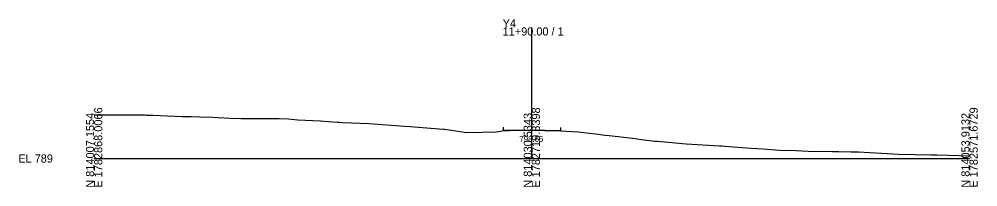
# Model space of a CAD drawing. Extents: x -26 to 3903, y -10 to 9562.
# Drawn here: x 2274.3 to 2602.8, y 490.3 to 547.7 of the extents above; entities that cross this region are included whole.
import ezdxf

# ---------------------------------------------------------------- set-up
doc = ezdxf.new("R2010")
doc.units = 0
for name, color, linetype in [('Exist Cross Section Cell', 7, 'Continuous'), ('Exist XS Center Line Elevation Label', 7, 'Continuous'), ('Exist XS Ground Line', 7, 'Continuous'), ('Prop XS EOT Tick Mark', 7, 'Continuous'), ('Prop XS Finish Grade Pavement', 7, 'Continuous')]:
    doc.layers.add(name, color=color, linetype=linetype)

msp = doc.modelspace()

# ---------------------------------------------------------------- linework, layer by layer
at = {"layer": 'Exist Cross Section Cell'}
for p, q in [((2450, 500), (2450, 544.86)), ((2300, 500), (2450, 500)), ((2450, 500), (2600, 500))]:
    msp.add_line(p, q, dxfattribs=at)
at = {"layer": 'Exist XS Ground Line'}
for p, q in [((2300, 514.94), (2302.74, 514.95)), ((2302.74, 514.95), (2317.36, 514.88)), ((2317.36, 514.88), (2317.93, 514.87)), ((2317.93, 514.87), (2320.13, 514.79)), ((2320.13, 514.79), (2330.17, 514.36)), ((2330.17, 514.36), (2333.2, 514.35)), ((2333.2, 514.35), (2336.09, 514.24)), ((2336.09, 514.24), (2340.7, 514.17)), ((2340.7, 514.17), (2342.54, 514.02)), ((2342.54, 514.02), (2346.5, 513.74)), ((2346.5, 513.74), (2350.32, 513.72)), ((2350.32, 513.72), (2355.28, 513.69)), ((2355.28, 513.69), (2363.4, 513.66)), ((2363.4, 513.66), (2366.62, 513.57)), ((2366.62, 513.57), (2369.82, 513.18)), ((2369.82, 513.18), (2377.54, 512.86)), ((2377.54, 512.86), (2378.72, 512.81)), ((2378.72, 512.81), (2383.42, 512.43)), ((2383.42, 512.43), (2384.03, 512.37)), ((2384.03, 512.37), (2385.08, 512.34)), ((2385.08, 512.34), (2394.29, 511.99)), ((2394.29, 511.99), (2406.19, 511.08)), ((2406.19, 511.08), (2408.38, 510.93)), ((2408.38, 510.93), (2409.66, 510.84)), ((2409.66, 510.84), (2419.74, 510.08)), ((2419.74, 510.08), (2420.07, 510.04)), ((2420.07, 510.04), (2421.81, 509.76)), ((2421.81, 509.76), (2427.48, 508.88)), ((2437.75, 509.08), (2439.34, 509.34)), ((2439.34, 509.34), (2440.34, 509.59)), ((2440.34, 509.59), (2442.38, 509.6)), ((2442.38, 509.6), (2450.02, 509.66)), ((2450.02, 509.66), (2454.49, 509.58)), ((2454.49, 509.58), (2459.95, 509.49)), ((2459.95, 509.49), (2463.9, 509.2)), ((2427.48, 508.88), (2432.82, 508.98)), ((2432.82, 508.98), (2437.75, 509.08)), ((2463.9, 509.2), (2465.92, 509.09)), ((2465.92, 509.09), (2472.82, 508.26)), ((2472.82, 508.26), (2474.97, 508.02)), ((2474.97, 508.02), (2476.49, 507.82)), ((2476.49, 507.82), (2484.56, 506.94)), ((2484.56, 506.94), (2487.53, 506.5)), ((2487.53, 506.5), (2492.1, 505.94)), ((2492.1, 505.94), (2492.97, 505.87)), ((2492.97, 505.87), (2502.91, 505.03)), ((2502.91, 505.03), (2514.35, 504.35)), ((2514.35, 504.35), (2515.04, 504.3)), ((2515.04, 504.3), (2516.12, 504.23)), ((2516.12, 504.23), (2525.19, 503.5)), ((2525.19, 503.5), (2529.22, 503.28)), ((2529.22, 503.28), (2534.92, 502.86)), ((2534.92, 502.86), (2540.45, 502.7)), ((2540.45, 502.7), (2544.67, 502.55)), ((2544.67, 502.55), (2553.07, 502.38)), ((2553.07, 502.38), (2554.03, 502.4)), ((2554.03, 502.4), (2555.17, 502.4)), ((2555.17, 502.4), (2559.38, 502.3)), ((2559.38, 502.3), (2561.62, 502.25)), ((2561.62, 502.25), (2561.97, 502.23)), ((2561.97, 502.23), (2575.62, 501.52)), ((2575.62, 501.52), (2586.83, 501.26)), ((2586.83, 501.26), (2588.91, 501.21)), ((2588.91, 501.21), (2592.74, 501.11)), ((2592.74, 501.11), (2600, 500.9))]:
    msp.add_line(p, q, dxfattribs=at)
at = {"layer": 'Prop XS EOT Tick Mark'}
for p, q in [((2440.34, 509.71), (2440.34, 510.71)), ((2459.95, 509.61), (2459.95, 510.61))]:
    msp.add_line(p, q, dxfattribs=at)
at = {"layer": 'Prop XS Finish Grade Pavement'}
for p, q in [((2440.34, 509.71), (2442.38, 509.72)), ((2442.38, 509.72), (2450.02, 509.79)), ((2450.03, 509.79), (2454.49, 509.71)), ((2454.49, 509.71), (2459.95, 509.61))]:
    msp.add_line(p, q, dxfattribs=at)

# ---------------------------------------------------------------- texts
at = {"layer": 'Exist Cross Section Cell'}
for s, p in [('Y4', (2440, 544.86)), ('11+90.00 / 1', (2440, 542.06)), ('EL 789', (2274, 498.6))]:
    msp.add_text(s, height=2.8, dxfattribs=at).set_placement(p)
for s, p in [('E 1782868.0066', (2302.8, 490)), ('E 1782719.8398', (2452.8, 490)), ('E 1782571.6729', (2602.8, 490)), ('N 814007.1554', (2300, 490)), ('N 814030.5343', (2450, 490)), ('N 814053.9132', (2600, 490))]:
    msp.add_text(s, height=2.8, rotation=90, dxfattribs=at).set_placement(p)
at = {"layer": 'Exist XS Center Line Elevation Label'}
msp.add_text('798.66', height=2, dxfattribs=at).set_placement((2445.73, 505.66))

doc.saveas('drawing.dxf')
